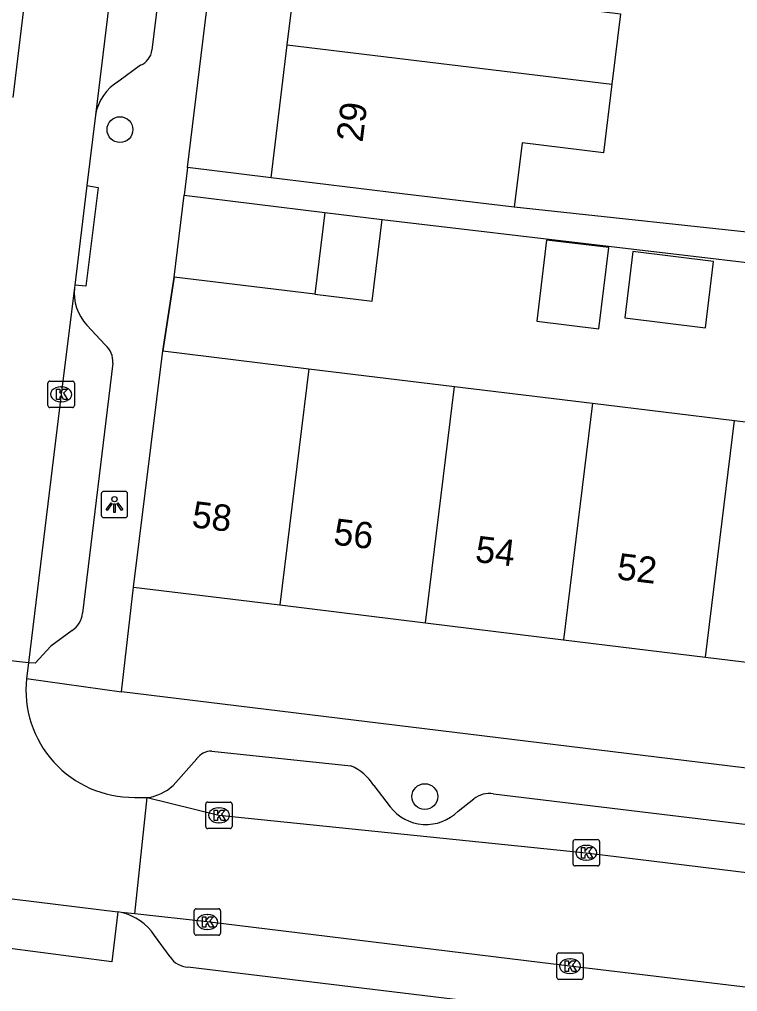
# Model space of a CAD drawing. Extents: x 158087 to 159494, y 382905 to 383981.
# Drawn here: x 158374.81 to 158402.03, y 383260.09 to 383296.93 of the extents above; entities that cross this region are included whole.
import ezdxf

# ---------------------------------------------------------------- set-up
doc = ezdxf.new("R2010")
doc.units = 0
for name, color, linetype in [('IMGEO_Boom', 7, 'Continuous'), ('IMGEO_Kolk', 7, 'Continuous'), ('IMGEO_Lichtpunt', 7, 'Continuous'), ('IMGEO_Muur', 7, 'Continuous'), ('IMGEO_Pand', 7, 'Continuous'), ('IMGEO_Pand_nummerreeks', 7, 'Continuous'), ('IMGEO_Rijbaan_lokaal_open', 7, 'Continuous'), ('IMGEO_Voetpad_open', 7, 'Continuous')]:
    doc.layers.add(name, color=color, linetype=linetype)

msp = doc.modelspace()

# ---------------------------------------------------------------- linework, layer by layer
at = {"layer": 'IMGEO_Boom'}
for centre in [(158378.623, 383292.755), (158390.179, 383267.475)]:
    msp.add_circle(centre, 0.489, dxfattribs=at)
at = {"layer": 'IMGEO_Kolk'}
for p, q in [((158375.894, 383282.297), (158375.894, 383283.149)), ((158375.969, 383283.223), (158376.821, 383283.223)), ((158376.895, 383283.149), (158376.895, 383282.297)), ((158376.382, 383283.003), (158376.407, 383283.003)), ((158376.405, 383282.443), (158376.38, 383282.443)), ((158376.821, 383282.223), (158375.969, 383282.223)), ((158381.948, 383267.267), (158382.8, 383267.267)), ((158381.873, 383266.341), (158381.873, 383267.193)), ((158382.361, 383267.047), (158382.386, 383267.047)), ((158382.874, 383267.193), (158382.874, 383266.341)), ((158382.384, 383266.487), (158382.359, 383266.487)), ((158382.8, 383266.267), (158381.948, 383266.267)), ((158395.798, 383264.921), (158395.798, 383265.773)), ((158395.873, 383265.847), (158396.725, 383265.847)), ((158396.799, 383265.773), (158396.799, 383264.921)), ((158396.286, 383265.627), (158396.311, 383265.627)), ((158396.309, 383265.067), (158396.284, 383265.067)), ((158396.725, 383264.847), (158395.873, 383264.847)), ((158381.51, 383263.224), (158382.362, 383263.224)), ((158381.435, 383262.298), (158381.435, 383263.15)), ((158381.923, 383263.004), (158381.948, 383263.004)), ((158382.436, 383263.15), (158382.436, 383262.298)), ((158381.946, 383262.444), (158381.921, 383262.444)), ((158382.362, 383262.224), (158381.51, 383262.224)), ((158395.181, 383260.624), (158395.181, 383261.476)), ((158395.256, 383261.55), (158396.108, 383261.55)), ((158395.669, 383261.33), (158395.694, 383261.33)), ((158396.182, 383261.476), (158396.182, 383260.624)), ((158395.692, 383260.77), (158395.667, 383260.77)), ((158396.108, 383260.55), (158395.256, 383260.55))]:
    msp.add_line(p, q, dxfattribs=at)
for points in [[(158375.894, 383282.297), (158375.894, 383283.149)], [(158375.969, 383283.223), (158376.821, 383283.223)], [(158376.895, 383283.149), (158376.895, 383282.297)], [(158376.215, 383282.923), (158376.338, 383282.923), (158376.338, 383282.772), (158376.468, 383282.923), (158376.632, 383282.923), (158376.486, 383282.772), (158376.639, 383282.523), (158376.487, 383282.523), (158376.402, 383282.687), (158376.338, 383282.62), (158376.338, 383282.523), (158376.215, 383282.523), (158376.215, 383282.923)], [(158376.821, 383282.223), (158375.969, 383282.223)], [(158381.948, 383267.267), (158382.8, 383267.267)], [(158381.873, 383266.341), (158381.873, 383267.193)], [(158382.194, 383266.967), (158382.317, 383266.967), (158382.317, 383266.816), (158382.447, 383266.967), (158382.611, 383266.967), (158382.465, 383266.816), (158382.618, 383266.567), (158382.466, 383266.567), (158382.381, 383266.731), (158382.317, 383266.664), (158382.317, 383266.567), (158382.194, 383266.567), (158382.194, 383266.967)], [(158382.874, 383267.193), (158382.874, 383266.341)], [(158382.8, 383266.267), (158381.948, 383266.267)], [(158395.798, 383264.921), (158395.798, 383265.773)], [(158395.873, 383265.847), (158396.725, 383265.847)], [(158396.799, 383265.773), (158396.799, 383264.921)], [(158396.119, 383265.547), (158396.242, 383265.547), (158396.242, 383265.396), (158396.372, 383265.547), (158396.536, 383265.547), (158396.39, 383265.396), (158396.543, 383265.147), (158396.391, 383265.147), (158396.306, 383265.311), (158396.242, 383265.244), (158396.242, 383265.147), (158396.119, 383265.147), (158396.119, 383265.547)], [(158396.725, 383264.847), (158395.873, 383264.847)], [(158381.51, 383263.224), (158382.362, 383263.224)], [(158381.435, 383262.298), (158381.435, 383263.15)], [(158381.756, 383262.924), (158381.879, 383262.924), (158381.879, 383262.773), (158382.009, 383262.924), (158382.173, 383262.924), (158382.027, 383262.773), (158382.18, 383262.524), (158382.028, 383262.524), (158381.943, 383262.688), (158381.879, 383262.621), (158381.879, 383262.524), (158381.756, 383262.524), (158381.756, 383262.924)], [(158382.436, 383263.15), (158382.436, 383262.298)], [(158382.362, 383262.224), (158381.51, 383262.224)], [(158395.181, 383260.624), (158395.181, 383261.476)], [(158395.256, 383261.55), (158396.108, 383261.55)], [(158396.182, 383261.476), (158396.182, 383260.624)], [(158395.502, 383261.25), (158395.625, 383261.25), (158395.625, 383261.099), (158395.755, 383261.25), (158395.919, 383261.25), (158395.773, 383261.099), (158395.926, 383260.85), (158395.774, 383260.85), (158395.689, 383261.014), (158395.625, 383260.947), (158395.625, 383260.85), (158395.502, 383260.85), (158395.502, 383261.25)], [(158396.108, 383260.55), (158395.256, 383260.55)]]:
    msp.add_lwpolyline(points, dxfattribs=at)
for centre, start, end in [((158375.971, 383283.147), 91.552, 178.448), ((158375.971, 383283.147), 91.552, 178.448), ((158376.819, 383283.147), 1.552, 88.448), ((158376.819, 383283.147), 1.552, 88.448), ((158375.971, 383282.299), 181.552, 268.448), ((158375.971, 383282.299), 181.552, 268.448), ((158376.819, 383282.299), 271.552, 358.448), ((158376.819, 383282.299), 271.552, 358.448), ((158381.95, 383267.191), 91.552, 178.448), ((158381.95, 383267.191), 91.552, 178.448), ((158382.798, 383267.191), 1.552, 88.448), ((158382.798, 383267.191), 1.552, 88.448), ((158381.95, 383266.343), 181.552, 268.448), ((158381.95, 383266.343), 181.552, 268.448), ((158382.798, 383266.343), 271.552, 358.448), ((158382.798, 383266.343), 271.552, 358.448), ((158395.875, 383265.771), 91.552, 178.448), ((158395.875, 383265.771), 91.552, 178.448), ((158396.723, 383265.771), 1.552, 88.448), ((158396.723, 383265.771), 1.552, 88.448), ((158395.875, 383264.923), 181.552, 268.448), ((158395.875, 383264.923), 181.552, 268.448), ((158396.723, 383264.923), 271.552, 358.448), ((158396.723, 383264.923), 271.552, 358.448), ((158381.512, 383263.148), 91.552, 178.448), ((158381.512, 383263.148), 91.552, 178.448), ((158382.36, 383263.148), 1.552, 88.448), ((158382.36, 383263.148), 1.552, 88.448), ((158381.512, 383262.3), 181.552, 268.448), ((158381.512, 383262.3), 181.552, 268.448), ((158382.36, 383262.3), 271.552, 358.448), ((158382.36, 383262.3), 271.552, 358.448), ((158395.258, 383261.474), 91.552, 178.448), ((158395.258, 383261.474), 91.552, 178.448), ((158396.106, 383261.474), 1.552, 88.448), ((158396.106, 383261.474), 1.552, 88.448), ((158395.258, 383260.626), 181.552, 268.448), ((158395.258, 383260.626), 181.552, 268.448), ((158396.106, 383260.626), 271.552, 358.448), ((158396.106, 383260.626), 271.552, 358.448)]:
    msp.add_arc(centre, 0.0765, start, end, dxfattribs=at)
for centre, major_axis, ratio, start_param, end_param in [((158376.381, 383282.723), (-0.387, 0.002), 0.722429, 4.712389, 7.853982), ((158376.406, 383282.723), (-0.39, 0.002), 0.717154, 1.570796, 4.712389), ((158382.36, 383266.767), (-0.387, 0.002), 0.722429, 4.712389, 7.853982), ((158382.385, 383266.767), (-0.39, 0.002), 0.717154, 1.570796, 4.712389), ((158396.285, 383265.347), (-0.387, 0.002), 0.722429, 4.712389, 7.853982), ((158396.31, 383265.347), (-0.39, 0.002), 0.717154, 1.570796, 4.712389), ((158381.922, 383262.724), (-0.387, 0.002), 0.722429, 4.712389, 7.853982), ((158381.947, 383262.724), (-0.39, 0.002), 0.717154, 1.570796, 4.712389), ((158395.668, 383261.05), (-0.387, 0.002), 0.722429, 4.712389, 7.853982), ((158395.693, 383261.05), (-0.39, 0.002), 0.717154, 1.570796, 4.712389)]:
    msp.add_ellipse(centre, major_axis=major_axis, ratio=ratio, start_param=start_param, end_param=end_param, dxfattribs=at)
at = {"layer": 'IMGEO_Lichtpunt'}
for p, q in [((158378.817, 383279.046), (158378.009, 383279.046)), ((158378.817, 383279.046), (158378.009, 383279.046)), ((158377.915, 383278.951), (158377.915, 383278.144)), ((158377.915, 383278.951), (158377.915, 383278.144)), ((158378.911, 383278.144), (158378.911, 383278.951)), ((158378.911, 383278.144), (158378.911, 383278.951)), ((158378.009, 383278.05), (158378.817, 383278.05)), ((158378.009, 383278.05), (158378.817, 383278.05))]:
    msp.add_line(p, q, dxfattribs=at)
for points in [[(158378.289, 383278.615), (158378.328, 383278.587), (158378.14, 383278.325), (158378.102, 383278.352), (158378.289, 383278.615)], [(158378.391, 383278.567), (158378.438, 383278.567), (158378.438, 383278.245), (158378.391, 383278.245), (158378.391, 383278.567)], [(158378.501, 383278.587), (158378.539, 383278.614), (158378.726, 383278.352), (158378.687, 383278.324), (158378.501, 383278.587)]]:
    msp.add_lwpolyline(points, dxfattribs=at)
msp.add_circle((158378.414, 383278.749), 0.0994, dxfattribs=at)
for centre, start, end in [((158378.009, 383278.951), 90, 180), ((158378.009, 383278.951), 90, 180), ((158378.817, 383278.951), 0, 90), ((158378.817, 383278.951), 0, 90), ((158378.009, 383278.144), 180, 270), ((158378.009, 383278.144), 180, 270), ((158378.817, 383278.144), 270, 0), ((158378.817, 383278.144), 270, 360)]:
    msp.add_arc(centre, 0.0946, start, end, dxfattribs=at)
at = {"layer": 'IMGEO_Muur'}
msp.add_lwpolyline([(158380.252, 383284.368), (158380.676, 383287.166)], dxfattribs=at)
at = {"layer": 'IMGEO_Pand'}
for points in [[(158384.966, 383295.973), (158385.577, 383300.974)], [(158394.79, 383299.852), (158394.734, 383299.394), (158394.62, 383298.457), (158394.505, 383297.52), (158397.596, 383297.142), (158397.27, 383294.473)], [(158384.35, 383290.931), (158384.966, 383295.973)], [(158384.966, 383295.973), (158397.27, 383294.473)], [(158397.27, 383294.473), (158396.954, 383291.878), (158393.862, 383292.256), (158393.564, 383289.82)], [(158393.564, 383289.82), (158389.314, 383290.325), (158384.35, 383290.931)], [(158380.676, 383287.166), (158381.056, 383290.272)], [(158381.056, 383290.272), (158386.387, 383289.62)], [(158386.387, 383289.62), (158386.007, 383286.514)], [(158386.007, 383286.514), (158388.176, 383286.249), (158388.556, 383289.355)], [(158386.387, 383289.62), (158388.556, 383289.355)], [(158397.147, 383288.282), (158394.793, 383288.569), (158394.418, 383285.491), (158396.772, 383285.204), (158397.147, 383288.282)], [(158397.76, 383285.618), (158400.814, 383285.246), (158401.121, 383287.763), (158398.066, 383288.135), (158397.76, 383285.618)], [(158386.007, 383286.514), (158380.676, 383287.166)], [(158379.14, 383275.417), (158380.252, 383284.368)], [(158380.252, 383284.368), (158385.78, 383283.695)], [(158385.78, 383283.695), (158384.683, 383274.739)], [(158385.78, 383283.695), (158391.305, 383283.022)], [(158390.208, 383274.063), (158391.305, 383283.022)], [(158391.305, 383283.022), (158396.532, 383282.385)], [(158396.532, 383282.385), (158395.434, 383273.424)], [(158396.532, 383282.385), (158401.912, 383281.73)], [(158400.815, 383272.766), (158401.912, 383281.73)], [(158401.912, 383281.73), (158407.004, 383281.11)], [(158379.14, 383275.417), (158384.683, 383274.739)], [(158384.683, 383274.739), (158390.208, 383274.063)], [(158390.208, 383274.063), (158395.434, 383273.424)], [(158395.434, 383273.424), (158400.815, 383272.766)], [(158400.815, 383272.766), (158405.906, 383272.143)]]:
    msp.add_lwpolyline(points, dxfattribs=at)
at = {"layer": 'IMGEO_Rijbaan_lokaal_open'}
for points in [[(158381.673, 383325.946), (158381.021, 383320.424), (158378.935, 383303.495), (158377.692, 383293.307)], [(158375.105, 383298.488), (158374.568, 383293.97)], [(158377.692, 383293.307), (158377.362, 383290.636)], [(158377.362, 383290.636), (158376.907, 383286.862)], [(158376.894, 383286.76), (158376.393, 383282.724), (158375.153, 383272.548)], [(158376.907, 383286.862), (158376.894, 383286.76)], [(158375.153, 383272.548), (158371.99, 383272.904)], [(158375.153, 383272.548), (158375.081, 383271.957)], [(158379.17, 383267.446), (158379.471, 383267.441), (158379.652, 383267.438)], [(158379.187, 383263.032), (158379.652, 383267.438)], [(158379.652, 383267.438), (158382.369, 383266.766), (158396.295, 383265.346), (158408.879, 383263.807), (158429.056, 383261.419)], [(158373.079, 383263.774), (158378.545, 383263.106)], [(158378.681, 383263.089), (158378.545, 383263.106)], [(158379.187, 383263.032), (158378.681, 383263.089)], [(158428.587, 383257.026), (158423.767, 383257.644), (158408.237, 383259.549), (158395.678, 383261.052), (158381.932, 383262.725), (158379.187, 383263.032)]]:
    msp.add_lwpolyline(points, dxfattribs=at)
msp.add_arc((158379.135, 383271.523), 4.077, 173.8901, 270.4915, dxfattribs=at)
at = {"layer": 'IMGEO_Voetpad_open'}
for points in [[(158381.184, 383291.317), (158390.318, 383366.17)], [(158383.25, 383323.716), (158379.834, 383295.767)], [(158379.397, 383295.197), (158378.581, 383294.588)], [(158381.184, 383291.317), (158381.056, 383290.272)], [(158384.35, 383290.931), (158381.184, 383291.317)], [(158377.362, 383290.636), (158377.791, 383290.558), (158377.334, 383286.819), (158376.907, 383286.862)], [(158404.442, 383288.641), (158403.913, 383288.706), (158393.564, 383289.82)], [(158388.556, 383289.355), (158405.723, 383287.322)], [(158380.676, 383287.166), (158380.252, 383284.368)], [(158377.367, 383285.348), (158378.066, 383284.595)], [(158378.355, 383283.904), (158377.198, 383274.429)], [(158378.675, 383271.448), (158379.14, 383275.417)], [(158376.808, 383273.769), (158375.998, 383273.182), (158375.407, 383272.539), (158375.153, 383272.548)], [(158375.081, 383271.957), (158378.675, 383271.448)], [(158432.372, 383264.887), (158378.675, 383271.448)], [(158382.106, 383269.199), (158387.375, 383268.643)], [(158380.635, 383267.899), (158381.53, 383268.909)], [(158388.243, 383267.903), (158388.865, 383267.09)], [(158391.436, 383266.926), (158392.035, 383267.387)], [(158392.774, 383267.581), (158426.571, 383263.495)], [(158378.545, 383263.106), (158378.31, 383261.219), (158372.892, 383261.916), (158373.079, 383263.774)], [(158380.528, 383261.399), (158379.933, 383262.217)], [(158408.772, 383257.673), (158381.189, 383261.016)]]:
    msp.add_lwpolyline(points, dxfattribs=at)
for centre, radius, start, end in [((158379.137, 383295.849), 0.702, 291.7577, 353.29), ((158379.526, 383292.983), 1.863, 120.4954, 169.9842), ((158378.723, 383286.587), 1.837, 174.6116, 222.4286), ((158377.528, 383283.964), 0.829, 355.8371, 49.5556), ((158376.336, 383274.493), 0.864, 303.0806, 355.761), ((158382.097, 383268.499), 0.7, 89.3, 144.1479), ((158386.623, 383266.881), 1.916, 32.2307, 66.8718), ((158379.439, 383269.17), 1.745, 277.004, 313.2465), ((158392.612, 383266.692), 0.903, 79.6863, 129.7321), ((158390.222, 383268.124), 1.706, 217.3083, 315.3919), ((158378.191, 383261.05), 2.097, 33.8089, 76.4778), ((158381.229, 383261.846), 0.831, 212.5533, 267.2685)]:
    msp.add_arc(centre, radius, start, end, dxfattribs=at)

# ---------------------------------------------------------------- texts
at = {"layer": 'IMGEO_Pand_nummerreeks'}
for s, rotation, p in [('29', 83.0367, (158387.816, 383292.253)), ('58', 353.0257, (158381.314, 383277.69)), ('56', 353.0257, (158386.684, 383277.033)), ('54', 353.0257, (158392.056, 383276.376)), ('52', 353.0257, (158397.426, 383275.719))]:
    msp.add_text(s, height=1, rotation=rotation, dxfattribs=at).set_placement(p)

doc.saveas('drawing.dxf')
